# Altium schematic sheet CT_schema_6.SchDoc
size 562 x 419 mm
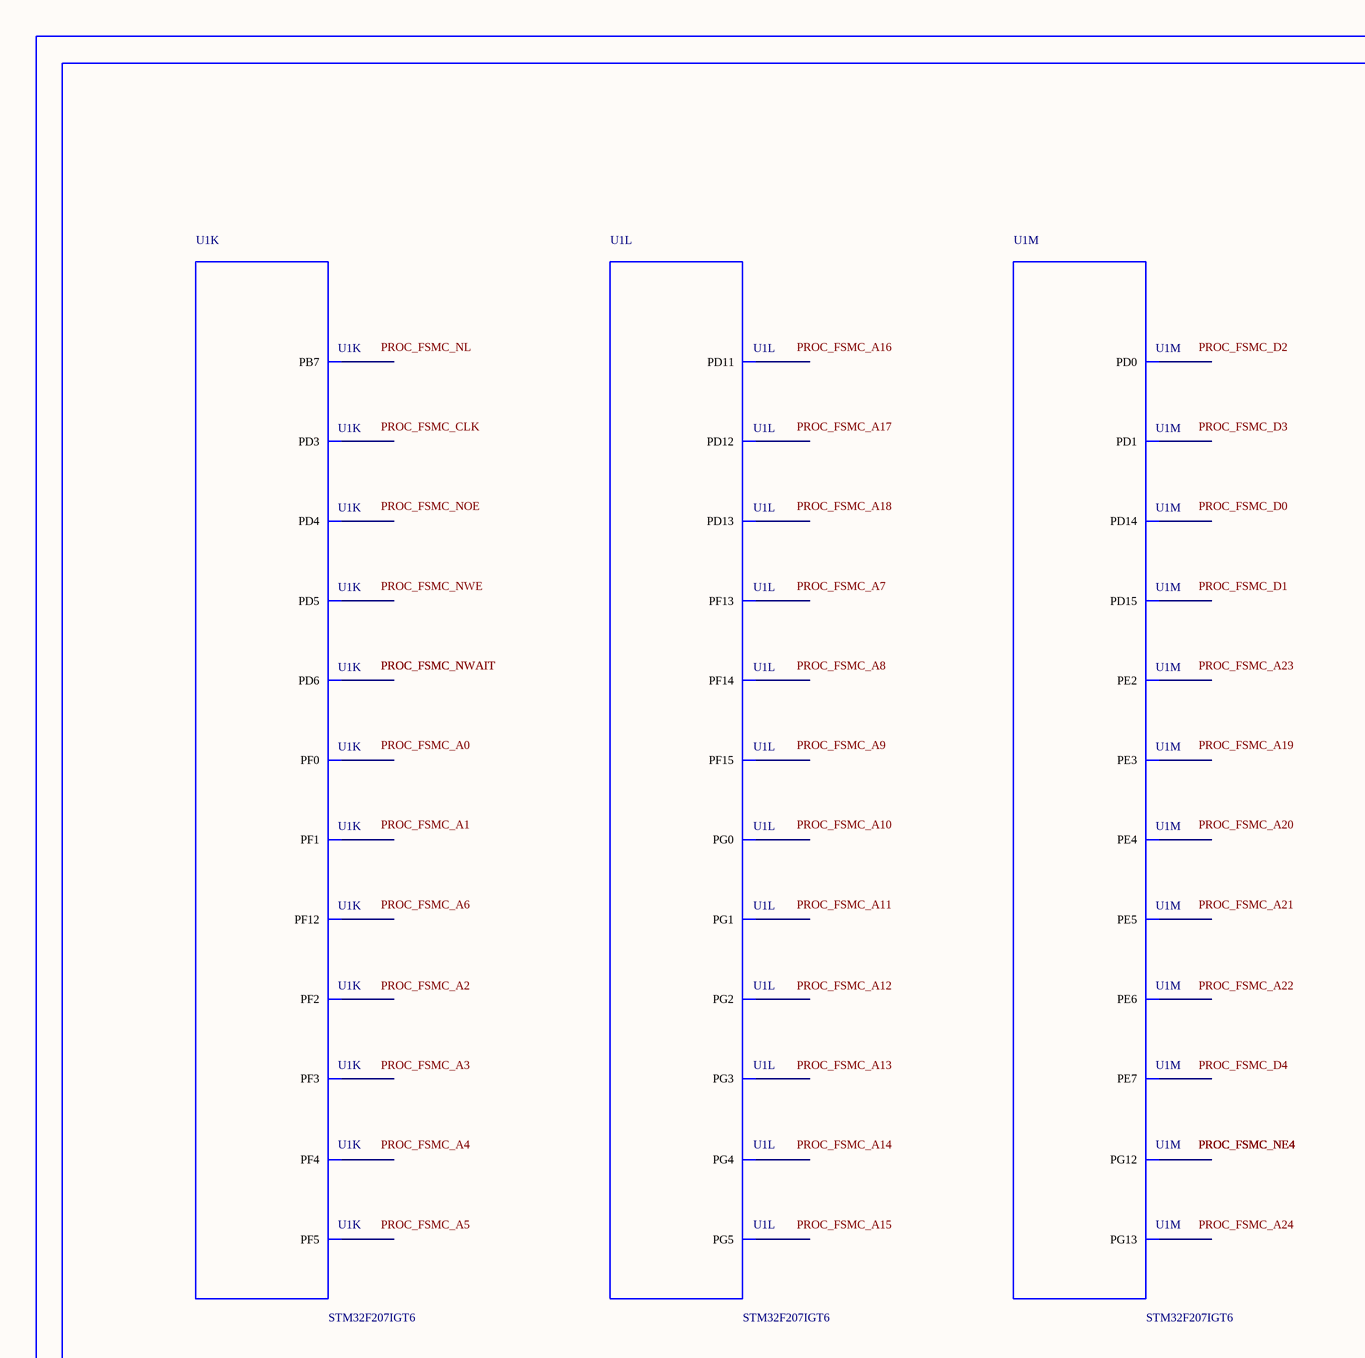
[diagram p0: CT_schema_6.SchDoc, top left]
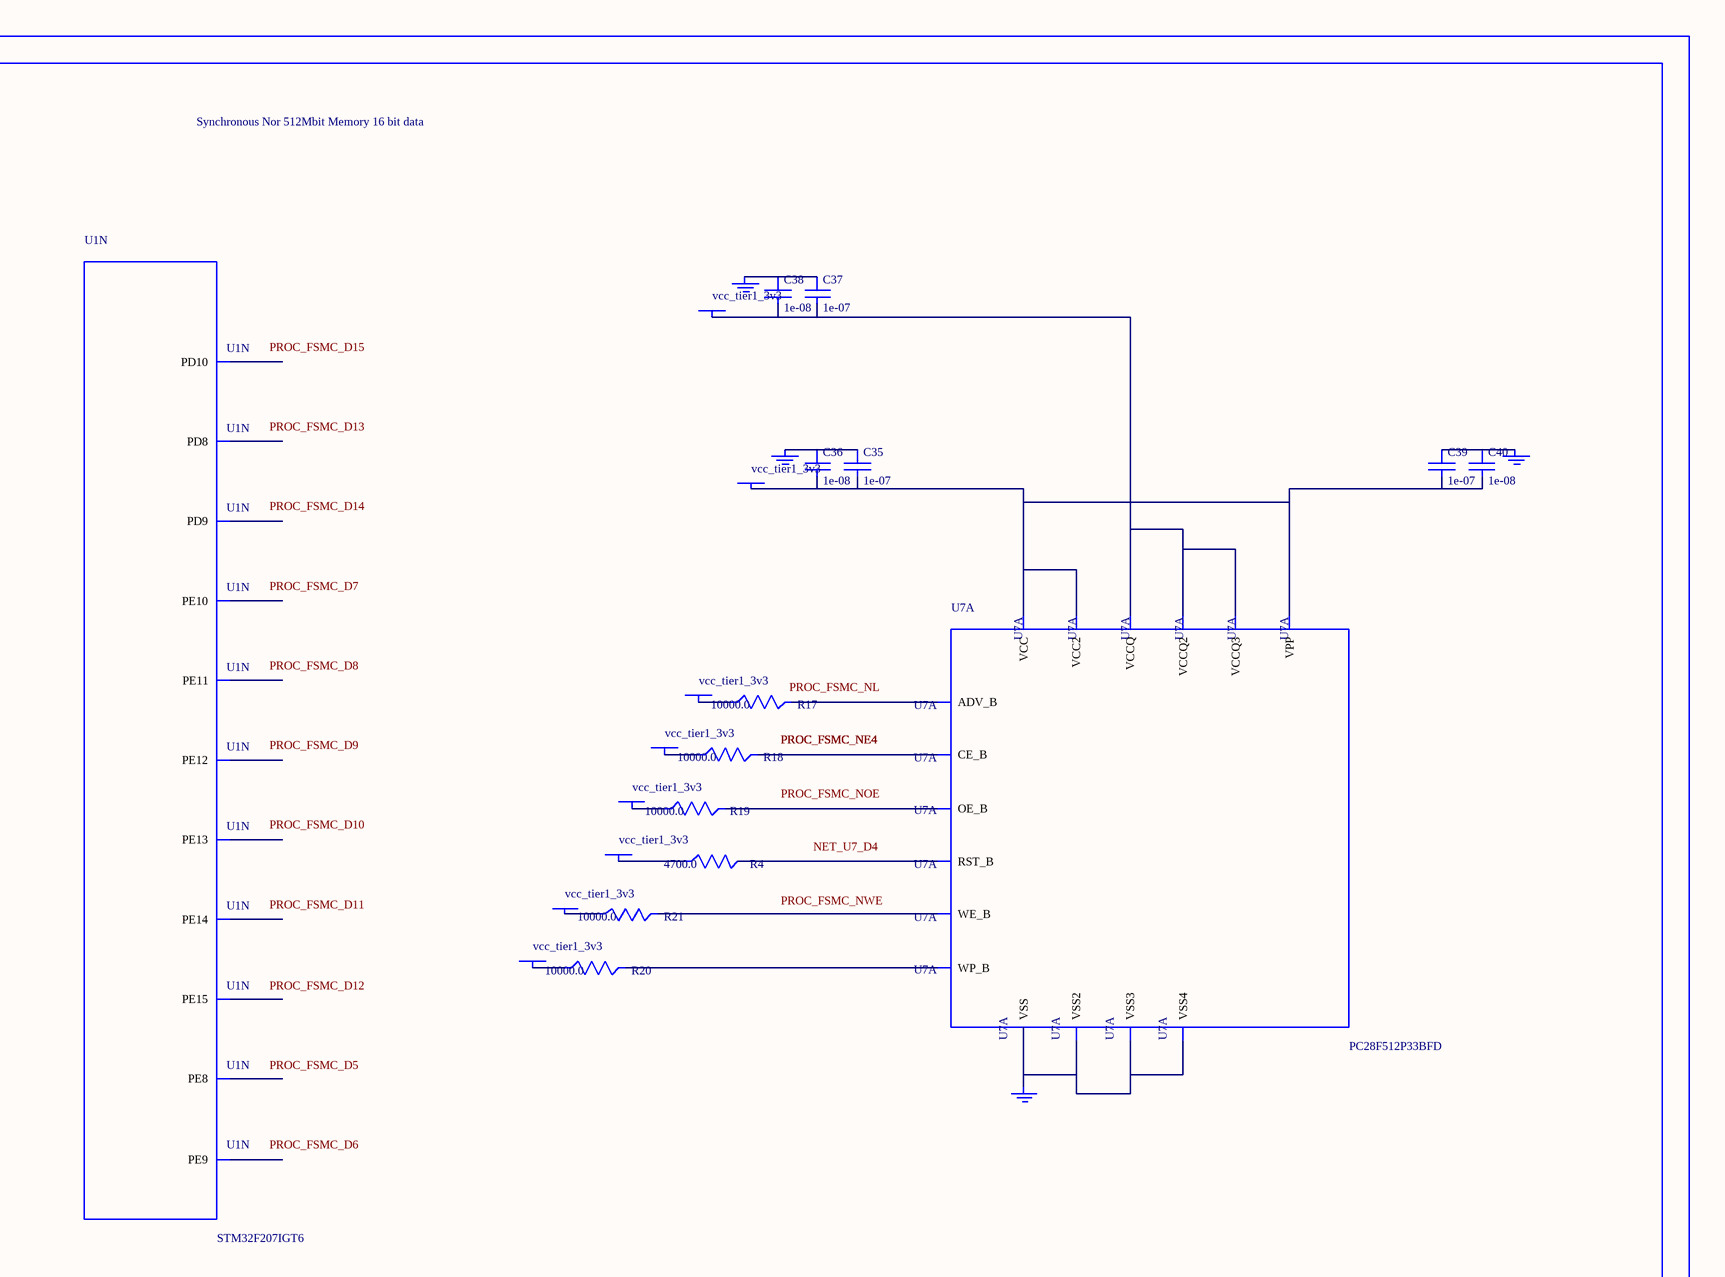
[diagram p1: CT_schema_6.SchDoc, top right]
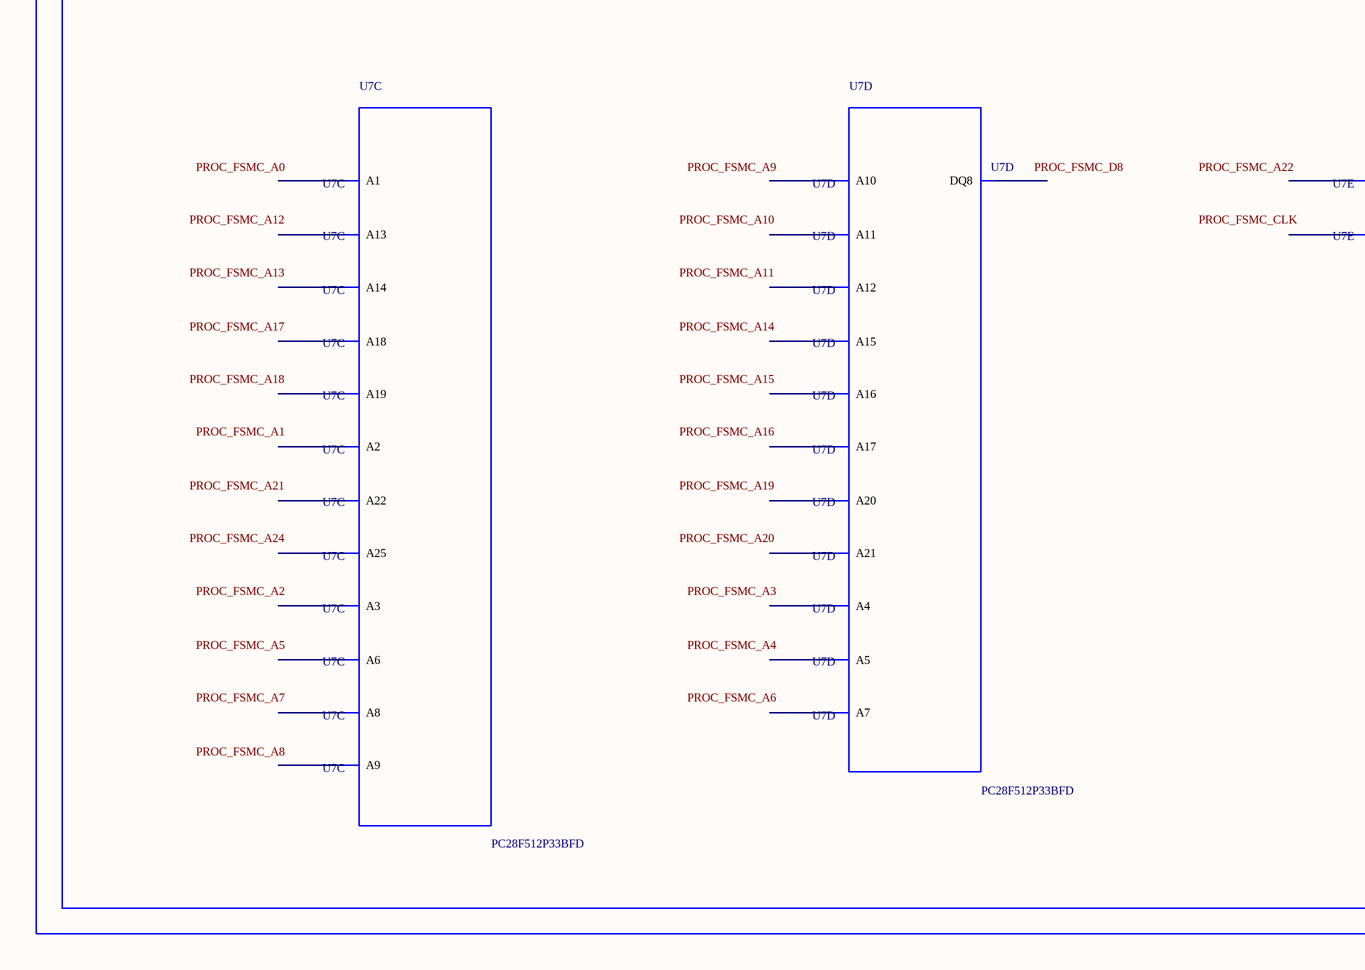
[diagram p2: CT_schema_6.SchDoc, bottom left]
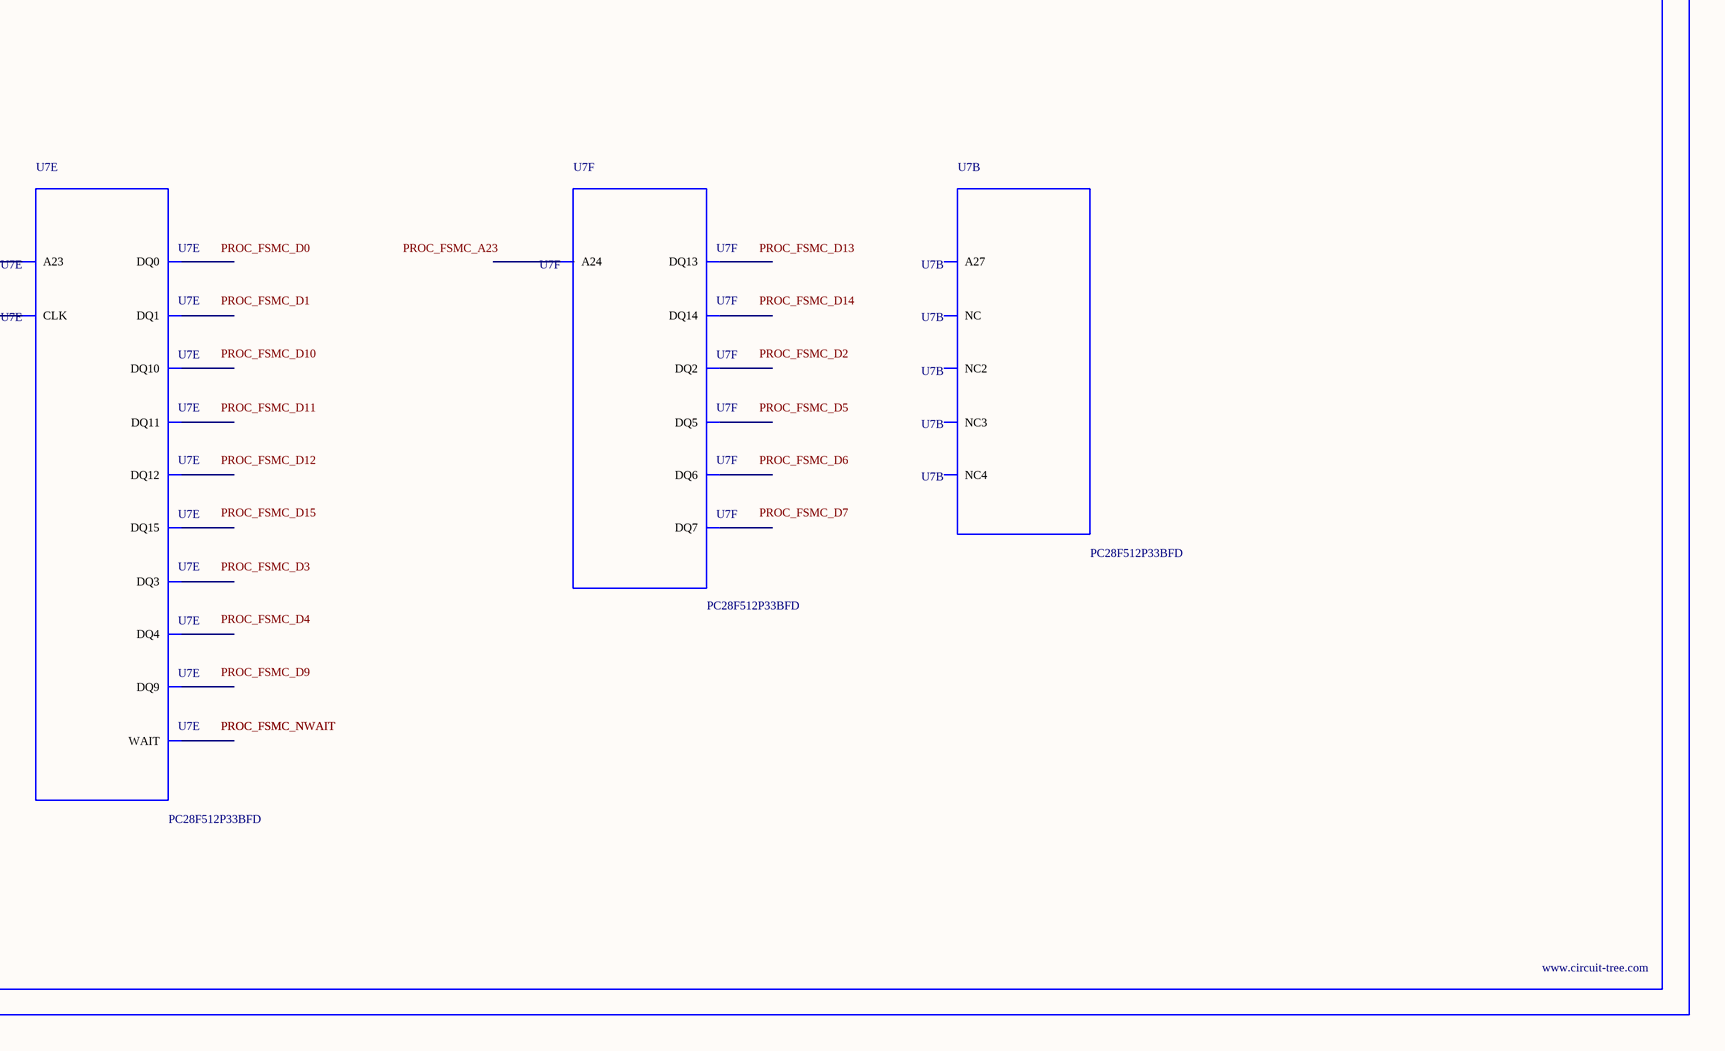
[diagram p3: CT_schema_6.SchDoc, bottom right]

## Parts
BORDER5  (no value)
C35  1e-07  [C0402]
C36  1e-08  [C0402]
C37  1e-07  [C0402]
C38  1e-08  [C0402]
C39  1e-07  [C0402]
C40  1e-08  [C0402]
GND_INSTANCE_5_0  (no value)
GND_INSTANCE_5_1  (no value)
GND_INSTANCE_5_2  (no value)
GND_INSTANCE_5_3  (no value)
POWER_INSTANCE_5_0  vcc_tier1_3v3
POWER_INSTANCE_5_1  vcc_tier1_3v3
POWER_INSTANCE_5_2  vcc_tier1_3v3
POWER_INSTANCE_5_3  vcc_tier1_3v3
POWER_INSTANCE_5_4  vcc_tier1_3v3
POWER_INSTANCE_5_5  vcc_tier1_3v3
POWER_INSTANCE_5_6  vcc_tier1_3v3
POWER_INSTANCE_5_7  vcc_tier1_3v3
R4  4700.0  [R0603]
R17  10000.0  [R0603]
R18  10000.0  [R0603]
R19  10000.0  [R0603]
R20  10000.0  [R0603]
R21  10000.0  [R0603]
U1  STM32F207IGT6  [LQFP176]  (parts K,L,M,N of 15)
U7  PC28F512P33BFD  [PC28F512P33BFD]  (parts A,B,C,D,E,F of 6)

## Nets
NetC35_1: C35.1 C36.1 GND_INSTANCE_5_0.0(GND)
NetC35_2: C35.2 C36.2 C39.2 C40.2 POWER_INSTANCE_5_0.0(PWR) U7.A4(VPP) U7.A6(VCC) U7.H3(VCC2)
NetC37_1: C37.1 C38.1 GND_INSTANCE_5_1.0(GND)
NetC37_2: C37.2 C38.2 POWER_INSTANCE_5_1.0(PWR) U7.D5(VCCQ) U7.D6(VCCQ2) U7.G4(VCCQ3)
NetC39_1: C39.1 C40.1 GND_INSTANCE_5_2.0(GND)
NetGND_INSTANCE_5_3_0: GND_INSTANCE_5_3.0(GND) U7.B2(VSS) U7.H2(VSS2) U7.H4(VSS3) U7.H6(VSS4)
NetPOWER_INSTANCE_5_2_0: POWER_INSTANCE_5_2.0(PWR) R17.1
NetPOWER_INSTANCE_5_3_0: POWER_INSTANCE_5_3.0(PWR) R18.1
NetPOWER_INSTANCE_5_4_0: POWER_INSTANCE_5_4.0(PWR) R19.1
NetPOWER_INSTANCE_5_5_0: POWER_INSTANCE_5_5.0(PWR) R20.1
NetPOWER_INSTANCE_5_6_0: POWER_INSTANCE_5_6.0(PWR) R21.1
NetPOWER_INSTANCE_5_7_0: POWER_INSTANCE_5_7.0(PWR) R4.1
NetR4_2: R4.2 U7.D4(RST_B)
NetR17_2: R17.2 U7.F6(ADV_B)
NetR18_2: R18.2 U7.B4(CE_B)
NetR19_2: R19.2 U7.F8(OE_B)
NetR20_2: R20.2 U7.C6(WP_B)
NetR21_2: R21.2 U7.G8(WE_B)

Not connected (* = marked no-connect by the designer): U1 1(PE2) 2(PE3) 3(PE4) 4(PE5) 5(PE6) 16(PF0) 17(PF1) 18(PF2) 19(PF3) 20(PF4) 21(PF5) 60(PF12) 63(PF13) 64(PF14) 65(PF15) 66(PG0) 67(PG1) 68(PE7) 69(PE8) 70(PE9) 73(PE10) 74(PE11) 75(PE12) 76(PE13) 77(PE14) 78(PE15) 96(PD8) 97(PD9) 98(PD10) 99(PD11) 100(PD12) 101(PD13) 104(PD14) 105(PD15) 106(PG2) 107(PG3) 108(PG4) 109(PG5) 142(PD0) 143(PD1) 145(PD3) 146(PD4) 147(PD5) 150(PD6) 155(PG12) 156(PG13) 165(PB7); U7 A1 A2(A6) A3(A8) A5(A13) A7(A18) A8(A22) B1(A2) B3(A9) B5(A14) B6(A25) B7(A19) B8(NC) C1(A3) C2(A7) C3(A10) C4(A12) C5(A15) C7(A20) C8(A21) D1(A4) D2(A5) D3(A11) D7(A16) D8(A17) E1(DQ8) E2(DQ1) E3(DQ9) E4(DQ3) E5(DQ4) E6(CLK) E7(DQ15) E8(NC2) F1(NC3) F2(DQ0) F3(DQ10) F4(DQ11) F5(DQ12) F7(WAIT) G1(A23) G2(NC4) G3(DQ2) G5(DQ5) G6(DQ6) G7(DQ14) H1(A27) H5(DQ13) H7(DQ7) H8(A24)

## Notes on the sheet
- Labels drawn without touching a wire or pin: NET_U7_D4, PROC_FSMC_A0, PROC_FSMC_A1, PROC_FSMC_A2, PROC_FSMC_A3, PROC_FSMC_A4, PROC_FSMC_A5, PROC_FSMC_A6, PROC_FSMC_A7, PROC_FSMC_A8, PROC_FSMC_A9, PROC_FSMC_A10, PROC_FSMC_A11, PROC_FSMC_A12, PROC_FSMC_A13, PROC_FSMC_A14, PROC_FSMC_A15, PROC_FSMC_A16, PROC_FSMC_A17, PROC_FSMC_A18, PROC_FSMC_A19, PROC_FSMC_A20, PROC_FSMC_A21, PROC_FSMC_A22, PROC_FSMC_A23, PROC_FSMC_A24, PROC_FSMC_CLK, PROC_FSMC_D0, PROC_FSMC_D1, PROC_FSMC_D2, PROC_FSMC_D3, PROC_FSMC_D4, PROC_FSMC_D5, PROC_FSMC_D6, PROC_FSMC_D7, PROC_FSMC_D8, PROC_FSMC_D9, PROC_FSMC_D10, PROC_FSMC_D11, PROC_FSMC_D12, PROC_FSMC_D13, PROC_FSMC_D14, PROC_FSMC_D15, PROC_FSMC_NL, PROC_FSMC_NOE, PROC_FSMC_NWE

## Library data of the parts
BORDER5 = BORDER_PAGE5
C35 C37 C39 = C0402C104K3RACTU
C36 C38 C40 = C0402C103K3RAC
GND_INSTANCE_5_0-GND_INSTANCE_5_3 = GND
POWER_INSTANCE_5_0-POWER_INSTANCE_5_7 = PWR
R4 = RC0603JR-074K7L
R17-R21 = RC0603JR-0710KL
